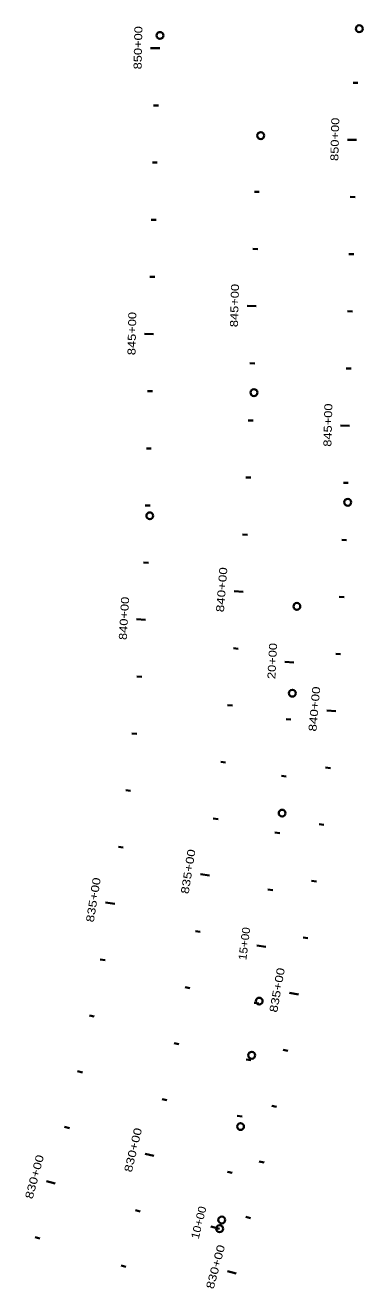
# Model space of a CAD drawing. Extents: x 2357892 to 2370172, y 6966790 to 6985499.
# Drawn here: x 2365976 to 2366565, y 6983290 to 6985499 of the extents above; entities that cross this region are included whole.
import ezdxf
from ezdxf.enums import TextEntityAlignment as Align

# ---------------------------------------------------------------- set-up
doc = ezdxf.new("R2010")
doc.units = 0
doc.header["$LTSCALE"] = 5.6
doc.layers.add('28', color=7, linetype='Continuous', lineweight=35)

msp = doc.modelspace()

# ---------------------------------------------------------------- linework, layer by layer
at = {"layer": '28'}
for p, q in [((2366210.444, 6985459.159), (2366194.448, 6985459.498)), ((2366556.868, 6985398.85), (2366548.371, 6985399.056)), ((2366208.324, 6985359.181), (2366199.826, 6985359.361)), ((2366554.44, 6985298.879), (2366538.445, 6985299.268)), ((2366206.204, 6985259.204), (2366197.705, 6985259.384)), ((2366384.319, 6985207.999), (2366375.822, 6985208.223)), ((2366552.011, 6985198.909), (2366543.514, 6985199.115)), ((2366204.083, 6985159.226), (2366195.585, 6985159.406)), ((2366381.687, 6985108.034), (2366373.19, 6985108.257)), ((2366549.583, 6985098.938), (2366541.086, 6985099.145)), ((2366201.963, 6985059.249), (2366193.464, 6985059.429)), ((2366379.055, 6985008.068), (2366363.06, 6985008.49)), ((2366547.155, 6984998.968), (2366538.657, 6984999.174)), ((2366199.842, 6984959.271), (2366183.846, 6984959.61)), ((2366376.422, 6984908.103), (2366367.925, 6984908.327)), ((2366544.726, 6984898.997), (2366536.229, 6984899.204)), ((2366197.722, 6984859.294), (2366189.223, 6984859.474)), ((2366373.607, 6984808.143), (2366365.112, 6984808.431)), ((2366542.298, 6984799.027), (2366526.303, 6984799.415)), ((2366195.601, 6984759.316), (2366187.103, 6984759.496)), ((2366369.455, 6984708.23), (2366360.965, 6984708.648)), ((2366539.87, 6984699.056), (2366531.372, 6984699.263)), ((2366193.481, 6984659.339), (2366184.982, 6984659.519)), ((2366363.766, 6984608.393), (2366355.284, 6984608.942)), ((2366537.06, 6984599.097), (2366528.566, 6984599.401)), ((2366190.679, 6984559.379), (2366182.185, 6984559.701)), ((2366356.543, 6984508.655), (2366340.594, 6984509.934)), ((2366532.608, 6984499.197), (2366524.12, 6984499.65)), ((2366185.89, 6984459.496), (2366169.917, 6984460.423)), ((2366347.785, 6984409.041), (2366339.324, 6984409.85)), ((2366445.016, 6984385.141), (2366429.037, 6984385.977)), ((2366526.412, 6984399.39), (2366517.933, 6984399.991)), ((2366179.085, 6984359.729), (2366170.611, 6984360.393)), ((2366337.497, 6984309.572), (2366329.049, 6984310.512)), ((2366518.475, 6984299.707), (2366502.538, 6984301.116)), ((2366439.625, 6984285.287), (2366431.142, 6984285.83)), ((2366170.266, 6984260.121), (2366161.807, 6984260.956)), ((2366325.679, 6984210.274), (2366317.246, 6984211.343)), ((2366431.496, 6984185.623), (2366423.037, 6984186.462)), ((2366508.8, 6984200.178), (2366500.348, 6984201.074)), ((2366159.437, 6984160.71), (2366150.996, 6984161.716)), ((2366312.335, 6984111.169), (2366303.92, 6984112.368)), ((2366497.39, 6984100.832), (2366488.954, 6984101.876)), ((2366420.112, 6984086.276), (2366411.675, 6984087.305)), ((2366146.601, 6984061.539), (2366138.183, 6984062.715)), ((2366297.468, 6984012.282), (2366281.665, 6984014.782)), ((2366408.007, 6983987.011), (2366399.569, 6983988.04)), ((2366484.247, 6984001.701), (2366475.831, 6984002.891)), ((2366131.765, 6983962.648), (2366115.967, 6983965.181)), ((2366281.082, 6983913.634), (2366272.707, 6983915.092)), ((2366469.376, 6983902.814), (2366460.982, 6983904.151)), ((2366395.901, 6983887.747), (2366380.019, 6983889.684)), ((2366114.935, 6983864.076), (2366106.571, 6983865.591)), ((2366263.179, 6983815.251), (2366254.829, 6983816.837)), ((2366383.793, 6983788.483), (2366375.357, 6983789.524)), ((2366452.782, 6983804.202), (2366437.027, 6983806.994)), ((2366096.116, 6983765.864), (2366087.785, 6983767.548)), ((2366243.766, 6983717.154), (2366235.441, 6983718.869)), ((2366434.469, 6983705.894), (2366426.127, 6983707.523)), ((2366369.824, 6983689.468), (2366361.425, 6983690.778)), ((2366075.317, 6983668.053), (2366067.022, 6983669.905)), ((2366222.846, 6983619.368), (2366214.548, 6983621.21)), ((2366354.412, 6983590.663), (2366346.014, 6983591.973)), ((2366414.443, 6983607.921), (2366406.131, 6983609.696)), ((2366052.547, 6983570.682), (2366044.291, 6983572.701)), ((2366200.423, 6983521.915), (2366184.859, 6983525.623)), ((2366392.711, 6983510.312), (2366384.43, 6983512.232)), ((2366337.247, 6983492.157), (2366328.913, 6983493.828)), ((2366027.815, 6983473.79), (2366012.353, 6983477.904)), ((2366176.505, 6983424.819), (2366168.267, 6983426.915)), ((2366369.278, 6983413.098), (2366361.032, 6983415.162)), ((2366315.093, 6983394.652), (2366299.559, 6983398.486)), ((2366001.13, 6983377.418), (2365992.962, 6983379.769)), ((2366151.095, 6983328.102), (2366142.891, 6983330.325)), ((2366344.152, 6983316.307), (2366328.701, 6983320.462))]:
    msp.add_line(p, q, dxfattribs=at)
for centre in [(2366559.166, 6985493.447), (2366210.921, 6985481.626), (2366386.913, 6985306.514), (2366375.075, 6984856.949), (2366539.046, 6984665.135), (2366193.102, 6984641.49), (2366450.136, 6984483.026), (2366442.195, 6984331.222), (2366424.409, 6984121.511), (2366384.311, 6983792.705), (2366371.154, 6983697.998), (2366351.707, 6983573.314), (2366318.873, 6983409.967), (2366315.093, 6983394.652)]:
    msp.add_circle(centre, 6, dxfattribs=at)

# ---------------------------------------------------------------- texts
for s, rotation, width, p in [('850+00', 88.785, 1.2, (2366179.454, 6985459.965)), ('850+00', 88.609, 1.2, (2366523.453, 6985299.802)), ('845+00', 88.492, 1.2, (2366348.07, 6985009.069)), ('845+00', 88.785, 1.2, (2366168.852, 6984960.078)), ('845+00', 88.609, 1.2, (2366511.311, 6984799.95)), ('840+00', 85.417, 1.25, (2366325.687, 6984511.692)), ('840+00', 86.677, 1.2, (2366154.966, 6984461.699)), ('20+00', 87.006, 1.2, (2366414.077, 6984387.126)), ('840+00', 84.948, 1.25, (2366487.65, 6984303.054)), ('835+00', 81.009, 1.25, (2366267.022, 6984018.221)), ('835+00', 80.889, 1.25, (2366101.334, 6983968.665)), ('15+00', 83.047, 1.1, (2366365.233, 6983892.347)), ('835+00', 79.948, 1.25, (2366422.475, 6983810.835)), ('830+00', 76.602, 1.25, (2366170.654, 6983530.721)), ('830+00', 75.102, 1.25, (2365998.336, 6983483.56)), ('10+00', 76.135, 1.1, (2366285.41, 6983403.759)), ('830+00', 74.948, 1.25, (2366314.705, 6983326.176))]:
    msp.add_text(s, height=14, rotation=rotation, dxfattribs=dict(at, width=width)).set_placement(p, align=Align.CENTER)

doc.saveas('drawing.dxf')
